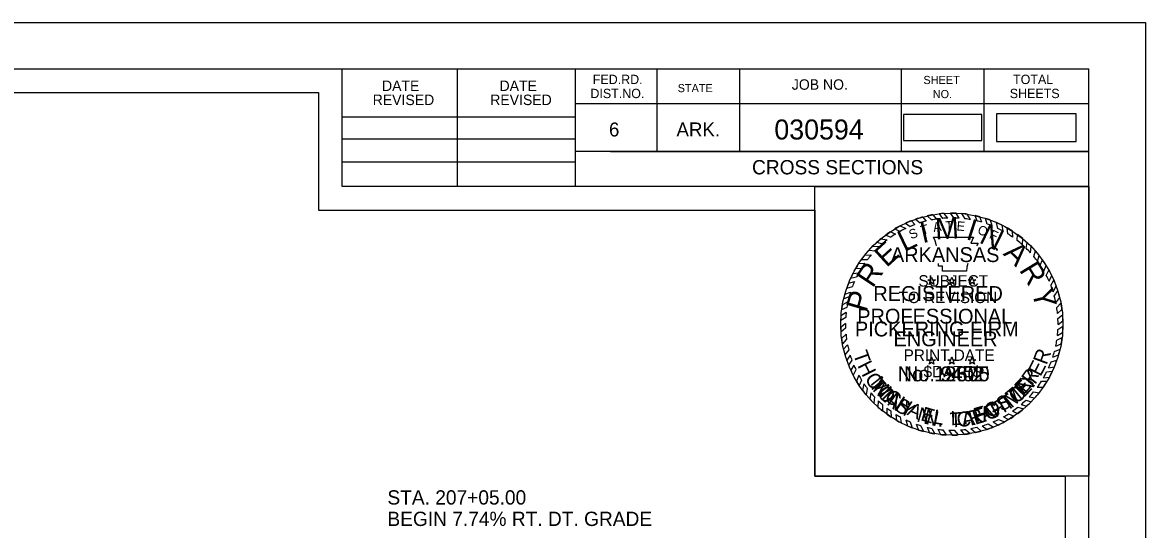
# Model space of a CAD drawing. Extents: x 1368713 to 1370673, y 380279 to 380950.
# Drawn here: x 1370578.3 to 1370672.6, y 380694.5 to 380737.1 of the extents above; entities that cross this region are included whole.
import ezdxf

# ---------------------------------------------------------------- set-up
doc = ezdxf.new("R2010")
doc.units = 0
for name, color, linetype in [('Notes', 7, 'Continuous'), ('R_Border', 7, 'Continuous'), ('R_Border Notes', 7, 'Continuous'), ('R_No Plot', 7, 'Continuous'), ('R_Water', 7, 'Continuous'), ('STAMP_PE_CRAFTON', 7, 'Continuous'), ('STAMP_PE_FOSTER', 7, 'Continuous'), ('STAMP_PE_SEAL-INFO', 7, 'Continuous'), ('STAMP_PE_TAEGTMEYER', 7, 'Continuous'), ('STAMP_PE_TXT', 7, 'Continuous'), ('STAMP_PRELIMINARY', 7, 'Continuous')]:
    doc.layers.add(name, color=color, linetype=linetype)

msp = doc.modelspace()

# ---------------------------------------------------------------- linework, layer by layer
at = {"layer": 'R_Border'}
for p, q in [((1370351.629, 380733.214), (1370667.809, 380733.214)), ((1370605.169, 380723.334), (1370605.169, 380733.214)), ((1370614.849, 380723.334), (1370614.849, 380733.214)), ((1370624.709, 380733.214), (1370624.709, 380723.334)), ((1370631.549, 380733.214), (1370631.549, 380726.274)), ((1370638.489, 380733.214), (1370638.489, 380726.274)), ((1370652.069, 380733.214), (1370652.069, 380726.274)), ((1370659.009, 380733.214), (1370659.009, 380726.274)), ((1370667.809, 380527.754), (1370667.809, 380733.214)), ((1370667.809, 380730.274), (1370624.709, 380730.274)), ((1370667.809, 380730.294), (1370667.809, 380730.294)), ((1370605.169, 380729.194), (1370624.709, 380729.194)), ((1370605.169, 380727.334), (1370624.709, 380727.334)), ((1370667.809, 380726.274), (1370624.709, 380726.274)), ((1370627.669, 380726.274), (1370667.809, 380726.274)), ((1370605.169, 380725.394), (1370624.709, 380725.394)), ((1370667.809, 380723.334), (1370605.169, 380723.334))]:
    msp.add_line(p, q, dxfattribs=at)
at = {"layer": 'R_No Plot'}
for points in [[(1370339.221, 380737.108), (1370672.561, 380737.108), (1370672.561, 380523.771), (1370339.221, 380523.771)], [(1370665.809, 380632.484), (1370353.629, 380632.484), (1370353.629, 380731.214), (1370603.169, 380731.214), (1370603.169, 380721.334), (1370620.709, 380721.334), (1370644.809, 380721.334), (1370644.809, 380699.001), (1370665.809, 380699.001)], [(1370353.629, 380731.214), (1370603.169, 380731.214), (1370603.169, 380721.334), (1370620.709, 380721.334), (1370644.809, 380721.334), (1370644.809, 380699.001), (1370665.809, 380699.001), (1370665.809, 380529.754), (1370353.629, 380529.754)], [(1370644.809, 380723.334), (1370667.809, 380723.334), (1370667.809, 380699.001), (1370644.809, 380699.001)]]:
    msp.add_lwpolyline(points, close=True, dxfattribs=at)
at = {"layer": 'R_Water'}
for points in [[(1370652.257, 380727.181), (1370658.821, 380727.181), (1370658.821, 380729.367), (1370652.257, 380729.367)], [(1370660.067, 380727.118), (1370666.751, 380727.118), (1370666.751, 380729.429), (1370660.067, 380729.429)]]:
    msp.add_lwpolyline(points, close=True, dxfattribs=at)
at = {"layer": 'STAMP_PE_SEAL-INFO'}
for p, q in [((1370652.413, 380720.246), (1370652.802, 380719.971)), ((1370652.921, 380720.461), (1370653.215, 380720.136)), ((1370653.268, 380720.589), (1370653.649, 380720.284)), ((1370653.859, 380720.771), (1370654.147, 380720.424)), ((1370654.247, 380720.868), (1370654.603, 380720.525)), ((1370654.73, 380720.964), (1370655.029, 380720.597)), ((1370655.245, 380721.038), (1370655.526, 380720.655)), ((1370655.981, 380720.684), (1370655.669, 380721.077)), ((1370656.479, 380720.688), (1370656.2, 380721.098)), ((1370656.937, 380720.668), (1370656.678, 380721.092)), ((1370657.442, 380720.617), (1370657.15, 380721.061)), ((1370657.868, 380720.552), (1370657.611, 380721.008)), ((1370658.43, 380720.434), (1370658.256, 380720.893)), ((1370658.832, 380720.325), (1370658.673, 380720.794)), ((1370659.284, 380720.179), (1370659.142, 380720.658)), ((1370659.702, 380720.019), (1370659.558, 380720.515)), ((1370660.163, 380719.813), (1370660.061, 380720.311)), ((1370651.147, 380719.539), (1370651.589, 380719.337)), ((1370651.534, 380719.783), (1370651.966, 380719.56)), ((1370651.982, 380720.034), (1370652.445, 380719.809)), ((1370660.609, 380719.584), (1370660.522, 380720.093)), ((1370660.997, 380719.357), (1370660.957, 380719.858)), ((1370661.431, 380719.071), (1370661.4, 380719.586)), ((1370661.792, 380718.804), (1370661.826, 380719.291)), ((1370650.006, 380718.645), (1370650.465, 380718.507)), ((1370650.35, 380718.946), (1370650.879, 380718.845)), ((1370650.727, 380719.273), (1370651.182, 380719.068)), ((1370654.782, 380719.068), (1370658.126, 380719.068)), ((1370654.903, 380718.76), (1370654.782, 380719.068)), ((1370655.007, 380718.462), (1370654.903, 380718.76)), ((1370655.014, 380718.348), (1370655.007, 380718.462)), ((1370658.126, 380719.068), (1370657.901, 380718.576)), ((1370657.901, 380718.576), (1370658.534, 380718.576)), ((1370658.534, 380718.576), (1370658.389, 380718.348)), ((1370662.238, 380718.432), (1370662.258, 380718.954)), ((1370662.551, 380718.139), (1370662.62, 380718.638)), ((1370649.002, 380717.566), (1370649.551, 380717.589)), ((1370649.348, 380717.978), (1370649.87, 380717.939)), ((1370649.671, 380718.322), (1370650.215, 380718.281)), ((1370662.91, 380717.766), (1370662.977, 380718.292)), ((1370663.184, 380717.45), (1370663.32, 380717.921)), ((1370663.508, 380717.032), (1370663.643, 380717.532)), ((1370648.244, 380716.452), (1370648.733, 380716.472)), ((1370648.49, 380716.853), (1370649.006, 380716.886)), ((1370648.724, 380717.197), (1370649.229, 380717.192)), ((1370655.206, 380716.639), (1370655.179, 380716.857)), ((1370655.52, 380716.639), (1370655.206, 380716.639)), ((1370655.52, 380716.209), (1370655.52, 380716.639)), ((1370657.565, 380716.547), (1370657.55, 380716.209)), ((1370657.643, 380716.857), (1370657.565, 380716.547)), ((1370663.728, 380716.717), (1370663.905, 380717.181)), ((1370664.036, 380716.22), (1370664.218, 380716.711)), ((1370647.824, 380715.639), (1370648.327, 380715.743)), ((1370648.012, 380716.028), (1370648.511, 380716.093)), ((1370657.55, 380716.209), (1370655.52, 380716.209)), ((1370664.235, 380715.853), (1370664.462, 380716.298)), ((1370664.466, 380715.369), (1370664.693, 380715.854)), ((1370647.49, 380714.801), (1370647.975, 380714.937)), ((1370647.641, 380715.207), (1370648.145, 380715.353)), ((1370664.607, 380715.032), (1370664.87, 380715.466)), ((1370664.801, 380714.483), (1370665.072, 380714.958)), ((1370647.593, 380713.644), (1370647.128, 380713.395)), ((1370647.229, 380713.89), (1370647.699, 380714.083)), ((1370647.334, 380714.298), (1370647.811, 380714.466)), ((1370664.909, 380714.119), (1370665.203, 380714.571)), ((1370665.042, 380713.56), (1370665.361, 380714.007)), ((1370647.449, 380712.75), (1370647.012, 380712.469)), ((1370647.508, 380713.185), (1370647.062, 380712.963)), ((1370665.111, 380713.18), (1370665.465, 380713.533)), ((1370665.177, 380712.671), (1370665.55, 380713.007)), ((1370647.412, 380712.324), (1370646.991, 380712.068)), ((1370647.396, 380711.831), (1370646.991, 380711.496)), ((1370665.21, 380712.253), (1370665.6, 380712.544)), ((1370665.222, 380711.735), (1370665.627, 380712.056)), ((1370647.402, 380711.424), (1370647.011, 380711.099)), ((1370647.436, 380710.929), (1370647.064, 380710.572)), ((1370665.171, 380710.823), (1370665.606, 380711.08)), ((1370665.211, 380711.329), (1370665.63, 380711.606)), ((1370647.487, 380710.5), (1370647.133, 380710.126)), ((1370647.566, 380710.041), (1370647.227, 380709.673)), ((1370665.03, 380709.935), (1370665.485, 380710.13)), ((1370665.121, 380710.435), (1370665.564, 380710.654)), ((1370647.66, 380709.622), (1370647.347, 380709.207)), ((1370647.783, 380709.175), (1370647.489, 380708.757)), ((1370664.775, 380708.989), (1370665.266, 380709.19)), ((1370664.922, 380709.483), (1370665.394, 380709.685)), ((1370647.924, 380708.752), (1370647.643, 380708.34)), ((1370648.091, 380708.325), (1370647.829, 380707.903)), ((1370664.427, 380708.095), (1370664.915, 380708.191)), ((1370664.641, 380708.609), (1370665.123, 380708.74)), ((1370648.262, 380707.942), (1370648.035, 380707.481)), ((1370648.497, 380707.484), (1370648.306, 380706.994)), ((1370648.733, 380707.08), (1370648.549, 380706.609)), ((1370663.993, 380707.26), (1370664.494, 380707.314)), ((1370664.266, 380707.758), (1370664.754, 380707.826)), ((1370648.935, 380706.768), (1370648.826, 380706.216)), ((1370649.216, 380706.378), (1370649.114, 380705.847)), ((1370663.482, 380706.485), (1370663.987, 380706.488)), ((1370663.822, 380706.979), (1370664.299, 380706.973)), ((1370649.52, 380706), (1370649.433, 380705.48)), ((1370649.823, 380705.663), (1370649.761, 380705.14)), ((1370650.145, 380705.337), (1370650.115, 380704.808)), ((1370662.536, 380705.399), (1370662.977, 380705.261)), ((1370662.791, 380705.658), (1370663.268, 380705.573)), ((1370663.174, 380706.091), (1370663.636, 380706.012)), ((1370650.49, 380705.025), (1370650.486, 380704.496)), ((1370650.849, 380704.73), (1370650.868, 380704.206)), ((1370651.188, 380704.481), (1370651.224, 380703.962)), ((1370661.055, 380704.231), (1370661.505, 380704.036)), ((1370661.399, 380704.459), (1370661.838, 380704.27)), ((1370661.86, 380704.802), (1370662.327, 380704.656)), ((1370662.13, 380705.026), (1370662.602, 380704.897)), ((1370651.615, 380704.199), (1370651.676, 380703.686)), ((1370651.965, 380703.993), (1370652.056, 380703.48)), ((1370652.446, 380703.743), (1370652.603, 380703.222)), ((1370652.819, 380703.574), (1370652.992, 380703.064)), ((1370653.311, 380703.382), (1370653.521, 380702.88)), ((1370659.354, 380703.399), (1370659.797, 380703.131)), ((1370659.774, 380703.564), (1370660.197, 380703.303)), ((1370660.233, 380703.773), (1370660.717, 380703.561)), ((1370660.641, 380703.986), (1370661.058, 380703.754)), ((1370653.721, 380703.247), (1370653.947, 380702.758)), ((1370654.229, 380703.109), (1370654.441, 380702.643)), ((1370654.626, 380703.023), (1370654.873, 380702.565)), ((1370655.127, 380702.941), (1370655.367, 380702.501)), ((1370655.563, 380702.894), (1370655.837, 380702.465)), ((1370656.048, 380702.867), (1370656.35, 380702.454)), ((1370656.508, 380702.865), (1370656.851, 380702.469)), ((1370657.026, 380702.892), (1370657.352, 380702.512)), ((1370657.465, 380702.938), (1370657.837, 380702.58)), ((1370657.91, 380703.008), (1370658.298, 380702.668)), ((1370658.402, 380703.112), (1370658.78, 380702.787)), ((1370658.862, 380703.236), (1370659.278, 380702.939))]:
    msp.add_line(p, q, dxfattribs=at)
for radius, start, end in [(9.323, 111.31242, 114.70259), (9.323, 105.23389, 109.03519), (8.914, 104.03521, 107.36155), (9.323, 99.75254, 102.77648), (8.914, 98.25799, 101.03289), (9.323, 93.93815, 96.55172), (8.914, 92.11016, 95.03666), (9.323, 87.72979, 90.67067), (8.914, 85.96279, 88.9097), (9.323, 81.97315, 84.82355), (8.914, 79.92642, 82.69597), (9.323, 75.31251, 77.94263), (8.914, 73.55748, 76.23144), (9.323, 69.60611, 72.30577), (9.323, 63.13288, 66.2704), (9.323, 123.61993, 126.59063), (8.914, 121.97456, 125.11001), (9.323, 117.65441, 120.80988), (8.914, 115.68692, 119.15827), (8.914, 110.30864, 113.16588), (8.914, 67.62483, 70.50398), (8.914, 61.15575, 64.37837), (9.323, 56.90029, 60.09423), (8.914, 54.92383, 58.27016), (9.323, 50.3492, 53.71593), (9.323, 129.73259, 132.53764), (8.914, 127.52969, 130.96829), (8.914, 48.30163, 52.03953), (9.323, 44.3405, 47.39292), (9.323, 141.60556, 144.44865), (8.914, 139.30101, 142.58729), (9.323, 135.40208, 138.30314), (8.914, 133.13306, 136.25623), (8.914, 42.22116, 45.55119), (8.914, 36.13503, 39.53106), (9.323, 38.12472, 41.23157), (9.323, 147.00719, 149.89904), (8.914, 145.01972, 148.21036), (8.914, 29.90321, 33.66454), (9.323, 31.96138, 35.42937), (9.323, 152.86398, 155.51889), (8.914, 151.03153, 153.57304), (8.914, 23.77322, 27.22114), (9.323, 25.93909, 29.01247), (9.323, 158.40766, 161.07015), (8.914, 156.34018, 159.23194), (8.914, 17.68022, 21.42509), (9.323, 19.95381, 23.31409), (9.323, 164.3068, 166.89395), (8.914, 167.90481, 170.90393), (8.914, 162.43309, 165.00133), (8.914, 11.54445, 15.23639), (9.323, 13.84205, 17.44468), (9.323, 170.0003, 172.68778), (8.914, 173.73, 176.47337), (8.914, 5.7599, 9.06056), (9.323, 7.58519, 10.86211), (9.323, 175.74093, 178.2066), (8.914, 179.64537, 182.26333), (8.914, 359.73289, 3.06392), (9.323, 1.72155, 4.72681), (9.323, 181.72508, 184.16255), (8.914, 185.45389, 188.23401), (8.914, 353.86319, 357.12742), (9.323, 355.71562, 358.95694), (9.323, 187.42037, 190.19271), (8.914, 191.22736, 193.98583), (8.914, 348.07782, 351.34355), (9.323, 349.83047, 353.08845), (9.323, 193.03695, 195.99732), (8.914, 196.96751, 199.83526), (8.914, 341.77699, 345.09248), (9.323, 343.89247, 347.03502), (9.323, 198.89671, 201.62812), (8.914, 202.77613, 205.47915), (8.914, 335.6038, 339.18578), (9.323, 337.38367, 340.99332), (9.323, 204.54793, 207.43282), (8.914, 208.78826, 211.79343), (8.914, 329.55488, 333.20757), (9.323, 331.40371, 334.93315), (9.323, 210.86355, 213.65709), (9.323, 216.61154, 219.49098), (8.914, 214.18375, 217.27474), (8.914, 323.58513, 327.44069), (9.323, 325.44052, 328.98725), (9.323, 222.47995, 225.38008), (8.914, 220.39088, 223.30564), (8.914, 226.24938, 229.24068), (8.914, 310.77436, 314.31605), (9.323, 312.45177, 315.66328), (8.914, 316.65308, 320.37109), (9.323, 318.28455, 321.80429), (9.323, 228.36648, 231.34802), (8.914, 232.22904, 234.93361), (8.914, 299.07679, 302.17235), (8.914, 304.82299, 308.51428), (9.323, 306.37206, 310.20799), (9.323, 234.29502, 236.94517), (8.914, 238.22227, 240.83529), (9.323, 240.1977, 242.86128), (8.914, 244.32043, 246.94859), (8.914, 250.34912, 253.12157), (8.914, 286.64233, 289.97826), (8.914, 292.87452, 296.11851), (9.323, 294.64808, 298.21662), (9.323, 300.62101, 303.87026), (9.323, 246.57598, 249.15579), (9.323, 252.59667, 255.32518), (8.914, 256.50505, 259.11916), (9.323, 258.44328, 261.13983), (8.914, 262.37828, 265.20115), (9.323, 264.19784, 267.10092), (8.914, 268.3215, 271.27698), (9.323, 270.25484, 273.33609), (8.914, 274.61565, 277.44863), (9.323, 276.42389, 279.43574), (8.914, 280.34588, 283.58137), (9.323, 282.31994, 285.37019), (9.323, 288.57086, 291.97334)]:
    msp.add_arc((1370656.309, 380711.776), radius, start, end, dxfattribs=at)
at = {"layer": 'STAMP_PE_TXT'}
for p, q in [((1370654.535, 380715.492), (1370654.611, 380715.725)), ((1370654.611, 380715.725), (1370654.687, 380715.492)), ((1370656.233, 380715.492), (1370656.309, 380715.725)), ((1370656.309, 380715.725), (1370656.385, 380715.492)), ((1370657.931, 380715.492), (1370658.007, 380715.725)), ((1370658.007, 380715.725), (1370658.083, 380715.492)), ((1370654.488, 380715.348), (1370654.29, 380715.492)), ((1370654.29, 380715.492), (1370654.535, 380715.492)), ((1370654.413, 380715.114), (1370654.488, 380715.348)), ((1370654.611, 380715.259), (1370654.413, 380715.114)), ((1370654.809, 380715.114), (1370654.611, 380715.259)), ((1370654.687, 380715.492), (1370654.932, 380715.492)), ((1370654.932, 380715.492), (1370654.734, 380715.348)), ((1370654.734, 380715.348), (1370654.809, 380715.114)), ((1370656.186, 380715.348), (1370655.988, 380715.492)), ((1370655.988, 380715.492), (1370656.233, 380715.492)), ((1370656.111, 380715.114), (1370656.186, 380715.348)), ((1370656.309, 380715.259), (1370656.111, 380715.114)), ((1370656.507, 380715.114), (1370656.309, 380715.259)), ((1370656.385, 380715.492), (1370656.63, 380715.492)), ((1370656.63, 380715.492), (1370656.432, 380715.348)), ((1370656.432, 380715.348), (1370656.507, 380715.114)), ((1370657.884, 380715.348), (1370657.686, 380715.492)), ((1370657.686, 380715.492), (1370657.931, 380715.492)), ((1370657.809, 380715.114), (1370657.884, 380715.348)), ((1370658.007, 380715.259), (1370657.809, 380715.114)), ((1370658.205, 380715.114), (1370658.007, 380715.259)), ((1370658.083, 380715.492), (1370658.328, 380715.492)), ((1370658.328, 380715.492), (1370658.13, 380715.348)), ((1370658.13, 380715.348), (1370658.205, 380715.114)), ((1370654.535, 380708.785), (1370654.611, 380709.018)), ((1370654.611, 380709.018), (1370654.687, 380708.785)), ((1370656.233, 380708.785), (1370656.309, 380709.018)), ((1370656.309, 380709.018), (1370656.385, 380708.785)), ((1370657.931, 380708.785), (1370658.007, 380709.018)), ((1370658.007, 380709.018), (1370658.083, 380708.785)), ((1370654.488, 380708.641), (1370654.29, 380708.785)), ((1370654.29, 380708.785), (1370654.535, 380708.785)), ((1370654.413, 380708.407), (1370654.488, 380708.641)), ((1370654.611, 380708.552), (1370654.413, 380708.407)), ((1370654.809, 380708.407), (1370654.611, 380708.552)), ((1370654.687, 380708.785), (1370654.932, 380708.785)), ((1370654.932, 380708.785), (1370654.734, 380708.641)), ((1370654.734, 380708.641), (1370654.809, 380708.407)), ((1370656.186, 380708.641), (1370655.988, 380708.785)), ((1370655.988, 380708.785), (1370656.233, 380708.785)), ((1370656.111, 380708.407), (1370656.186, 380708.641)), ((1370656.309, 380708.552), (1370656.111, 380708.407)), ((1370656.507, 380708.407), (1370656.309, 380708.552)), ((1370656.385, 380708.785), (1370656.63, 380708.785)), ((1370656.63, 380708.785), (1370656.432, 380708.641)), ((1370656.432, 380708.641), (1370656.507, 380708.407)), ((1370657.884, 380708.641), (1370657.686, 380708.785)), ((1370657.686, 380708.785), (1370657.931, 380708.785)), ((1370657.809, 380708.407), (1370657.884, 380708.641)), ((1370658.007, 380708.552), (1370657.809, 380708.407)), ((1370658.205, 380708.407), (1370658.007, 380708.552)), ((1370658.083, 380708.785), (1370658.328, 380708.785)), ((1370658.328, 380708.785), (1370658.13, 380708.641)), ((1370658.13, 380708.641), (1370658.205, 380708.407))]:
    msp.add_line(p, q, dxfattribs=at)
at = {"layer": 'STAMP_PRELIMINARY'}
msp.add_circle((1370656.309, 380711.776), 9.323, dxfattribs=at)

# ---------------------------------------------------------------- texts
at = {"layer": 'Notes'}
for s, p in [('STA. 207+05.00', (1370608.962, 380696.624)), ('BEGIN 7.74% RT. DT. GRADE', (1370608.962, 380694.824))]:
    msp.add_text(s, height=1.2, dxfattribs=at).set_placement(p)
at = {"layer": 'R_Border'}
for s, height, p in [('FED.RD.', 0.7819, (1370626.189, 380731.934)), ('SHEET', 0.684, (1370653.929, 380731.934)), ('TOTAL', 0.7819, (1370661.449, 380731.934)), ('DATE', 0.8792, (1370608.507, 380731.35)), ('DATE', 0.8792, (1370618.367, 380731.35)), ('DIST.NO.', 0.7819, (1370625.989, 380730.754)), ('STATE', 0.684, (1370633.309, 380731.254)), ('JOB NO.', 0.8792, (1370642.889, 380731.454)), ('SHEETS', 0.7819, (1370661.169, 380730.754)), ('REVISED', 0.8792, (1370607.727, 380730.17)), ('REVISED', 0.8792, (1370617.587, 380730.17)), ('NO.', 0.684, (1370654.709, 380730.754)), ('6', 1.172, (1370627.549, 380727.534)), ('ARK.', 1.1723, (1370633.209, 380727.534))]:
    msp.add_text(s, height=height, rotation=360, dxfattribs=at).set_placement(p)
at = {"layer": 'R_Border Notes'}
for s, height, p in [('030594', 1.68, (1370641.42, 380727.279)), ('CROSS SECTIONS', 1.2, (1370639.548, 380724.352))]:
    msp.add_text(s, height=height, rotation=360, dxfattribs=at).set_placement(p)
at = {"layer": 'STAMP_PE_CRAFTON'}
for s, rotation, p in [('No. 12370', 360, (1370651.771, 380706.973)), ('T', 310.74416, (1370649.275, 380706.674)), ('N', 49.24107, (1370662.591, 380705.798)), ('O', 317.64216, (1370649.942, 380705.863)), ('O', 41.83906, (1370661.744, 380705.017)), ('N', 324.45371, (1370650.788, 380705.078)), ('Y', 331.16864, (1370651.821, 380704.362)), ('F', 28.78207, (1370659.97, 380703.906)), ('T', 34.11362, (1370660.886, 380704.415)), ('N', 347.47515, (1370653.876, 380703.446)), ('C', 6.01169, (1370656.78, 380703.117)), ('R', 14.81888, (1370657.877, 380703.232)), ('A', 20.51248, (1370658.99, 380703.532)), ('.', 356.89262, (1370655.105, 380703.169))]:
    msp.add_text(s, height=1.25, rotation=rotation, dxfattribs=at).set_placement(p)
at = {"layer": 'STAMP_PE_FOSTER'}
for s, height, rotation, p in [('No. 9402', 1.25, 360, (1370652.295, 380706.973)), ('R', 1.2, 54.5031, (1370663.033, 380706.587)), ('M', 1.2, 308.33902, (1370649.425, 380706.798)), ('E', 1.2, 46.96131, (1370662.31, 380705.766)), ('I', 1.2, 314.18423, (1370650.223, 380705.861)), ('C', 1.2, 319.87327, (1370650.577, 380705.507)), ('T', 1.2, 39.41938, (1370661.451, 380705.016)), ('H', 1.2, 327.72349, (1370651.506, 380704.771)), ('O', 1.2, 23.71897, (1370659.388, 380703.859)), ('S', 1.2, 31.72336, (1370660.5, 380704.389)), ('A', 1.2, 335.72761, (1370652.487, 380704.189)), ('E', 1.2, 343.5779, (1370653.624, 380703.719)), ('L', 1.2, 350.81148, (1370654.683, 380703.441)), ('L', 1.2, 1.26658, (1370656.222, 380703.285)), ('F', 1.2, 15.86908, (1370658.344, 380703.531)), ('.', 1.2, 6.80354, (1370657.269, 380703.343))]:
    msp.add_text(s, height=height, rotation=rotation, dxfattribs=at).set_placement(p)
at = {"layer": 'STAMP_PE_TAEGTMEYER'}
for s, rotation, p in [('T', 289.64597, (1370648.003, 380709.286)), ('R', 69.57001, (1370664.254, 380708.291)), ('H', 296.73386, (1370648.363, 380708.302)), ('No. 19605', 360, (1370651.771, 380706.973)), ('E', 63.0984, (1370663.755, 380707.309)), ('O', 303.77078, (1370648.956, 380707.194)), ('E', 46.80938, (1370662.347, 380705.554)), ('Y', 53.99864, (1370663.086, 380706.369)), ('M', 314.20329, (1370649.611, 380706.243)), ('M', 39.30005, (1370661.307, 380704.674)), ('A', 321.0594, (1370650.573, 380705.278)), ('S', 327.82385, (1370651.399, 380704.634)), ('T', 31.46601, (1370660.409, 380704.131)), ('N', 344.27273, (1370653.296, 380703.628)), ('T', 3.00609, (1370656.173, 380703.097)), ('A', 8.98261, (1370657.22, 380703.152)), ('E', 17.68363, (1370658.259, 380703.308)), ('G', 23.30524, (1370659.309, 380703.638)), ('.', 350.64643, (1370654.508, 380703.296))]:
    msp.add_text(s, height=1.25, rotation=rotation, dxfattribs=at).set_placement(p)
at = {"layer": 'STAMP_PE_TXT'}
for s, height, rotation, p in [('A', 0.781, 9.0679, (1370654.793, 380719.505)), ('T', 0.781, 1.82479, (1370655.779, 380719.634)), ('E', 0.781, 355.20019, (1370656.69, 380719.643)), ('S', 0.781, 23.5541, (1370652.908, 380718.88)), ('T', 0.781, 16.311, (1370653.831, 380719.252)), ('O', 0.781, 342.25065, (1370658.416, 380719.366)), ('F', 0.781, 335.00755, (1370659.382, 380719.028)), ('ARKANSAS', 1.25, 360, (1370651.201, 380716.987)), ('REGISTERED', 1.25, 360, (1370649.726, 380713.717)), ('PROFESSIONAL', 1.25, 360, (1370648.377, 380711.816)), ('ENGINEER', 1.25, 360, (1370651.418, 380709.914))]:
    msp.add_text(s, height=height, rotation=rotation, dxfattribs=at).set_placement(p)
at = {"layer": 'STAMP_PRELIMINARY'}
for s, height, rotation, p in [('I', 1.8, 12.52485, (1370653.847, 380718.563)), ('M', 1.8, 3.10738, (1370654.945, 380718.872)), ('I', 1.8, 342.31637, (1370657.412, 380718.939)), ('L', 1.8, 25.51305, (1370652.318, 380717.804)), ('N', 1.8, 333.9382, (1370658.52, 380718.665)), ('E', 1.8, 42.35784, (1370650.835, 380716.473)), ('A', 1.8, 315.65789, (1370660.554, 380717.64)), ('R', 1.8, 56.22922, (1370649.68, 380714.74)), ('R', 1.8, 301.38306, (1370661.922, 380716.326)), ('SUBJECT', 0.96, 360, (1370653.509, 380714.926)), ('Y', 1.8, 283.25926, (1370663.011, 380714.539)), ('P', 1.8, 73.91301, (1370649.13, 380712.717)), ('TO REVISION', 0.96, 360, (1370651.844, 380713.541)), ('PICKERING FIRM', 1.25, 360, (1370648.182, 380710.739)), ('PRINT DATE', 0.96, 360, (1370652.266, 380708.692)), ('$DATE$', 0.96, 360, (1370653.943, 380707.307))]:
    msp.add_text(s, height=height, rotation=rotation, dxfattribs=at).set_placement(p)

doc.saveas('drawing.dxf')
